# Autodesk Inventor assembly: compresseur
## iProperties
Author: poste-2
Shininess: 41.0
Angle Display Precision: 2
Document Length Units: 11269
Document Angle Units: 11283
Document Time Units: 11279
Document Mass Units: 11290
Document Length Units Precision: 3
Document Angle Units Precision: 2
Compacted: False
PropertySet Name: _Private Model Information
Created: 2002-11
Part Number: compresseur
Document SubType Name: Assemblage
Designer: poste-2
Control State: 0
Master: False
Checked Out: False
PropertySet Name: Design Tracking Control
Density: 0.0
Volumn: 0.0
Area: 0.0
PropertySet Name: Model Information
